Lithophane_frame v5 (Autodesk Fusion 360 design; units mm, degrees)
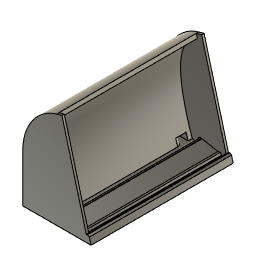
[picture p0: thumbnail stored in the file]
sketch "Sketch1" plane through (0, 0, 0) normal (0, 1, 0) x axis (1, 0, 0)
  line L1 (-20, -10) -> (0, -6)
  line L2 (-68.8984, 0) -> (-68.8984, -60)
  line L3 (16.1016, 0) -> (-68.8984, 0)
  line L4 (13.523, -9.6235) -> (16.1016, 0)
  line L5 (22.5, 0) -> (1.75, 0)
  line L6 (0, -22.5) -> (0, -1.75)
  line L7 (-20.1396, -121.7309) -> (-26.9011, -119.9192)
  line L8 (10.9187, -5.8198) -> (-20.1396, -121.7309)
  line L9 (4.1572, -4.0081) -> (10.9187, -5.8198)
  line L10 (-26.9011, -119.9192) -> (4.1572, -4.0081)
  line L11 (8.469, -1.439) -> (2.4963, -23.7296)
  line L12 (10.9187, -5.8198) -> (10.1422, -8.7176)
  line L13 (10.9187, -5.8198) -> (10.1422, -8.7176)
  line L14 (10.9187, -5.8198) -> (4.1572, -4.0081)
  line L15 (3.3807, -6.9059) -> (4.1572, -4.0081)
  line L16 (10.1422, -8.7176) -> (13.523, -9.6235)
  line L17 (0, -6) -> (3.3807, -6.9059)
  line L18 (-25.607, -115.0896) -> (-26.9011, -119.9192)
  line L19 (-25, -10) -> (-20, -10)
  line L20 (-25, -4) -> (-25, -10)
  line L21 (-32, -4) -> (-25, -4)
  curve K1 (-63.7939, -97.9077) -> (-25.607, -115.0896)
  curve K2 (-68.8984, -108.666) -> (-26.9011, -119.9192)
  line L22 (-45.6581, -60) -> (-68.8984, -60)
  point P3 (0, -6)
  point P14 (10.9187, -5.8198)
  point P15 (4.1572, -4.0081)
  point P2 (13.523, -9.6235)
  point P18 (10.1422, -8.7176)
  point P19 (3.3807, -6.9059)
  point P20 (-25.607, -115.0896)
  point P26 (-45.6581, -60)
  point P21 (-25, -10)
  point P22 (-25, -4)
  point P4 (-20, -10)
  point P12 (-26.9011, -119.9192)
  point P5 (-68.8984, -60)
  point P6 (-68.8984, 0)
  point P7 (16.1016, 0)
  point P23 (-32, -4)
  point P13 (-20.1396, -121.7309)
  perpendicular L2 L3
  perpendicular L4 L16
  collinear L3 L5
  coincident P3 L6
  perpendicular L7 L10
  perpendicular L7 L8
  perpendicular L8 L9
  parallel L4 L8
  parallel L4 L11
  symmetric P14 P15 L11
  symmetric P2 P3 L11
  coincident L8 P18
  coincident L10 P19
  coincident P19 L16
  collinear L16 L17
  coincident L10 P20
  perpendicular L7 L18
  horizontal L19
  perpendicular L19 L20
  perpendicular L20 L21
  coincident K1 P26
  perpendicular L2 L22
  dimension "d1" angle L3 L4 = 75
  dimension "d2" distance P2 P3 = 14
  dimension "d3" distance P3 L3 = 6
  dimension "d6" distance P14 P15 = 7
  dimension "d7" distance L9 L16 = 3
  dimension "d9" distance P21 P22 = 6
  dimension "d10" distance P4 P21 = 5
  dimension "d11" distance P12 P20 = 5
  dimension "d12" distance P5 P6 = 60
  dimension "d13" distance P5 P26 = 23.2403
  dimension "d14" distance P6 P7 = 85
  dimension "d15" distance L3 L21 = 4
  dimension "d16" distance P22 P23 = 7
  dimension "d17" distance P3 L20 = 25
  dimension "d20" distance P13 P14 = 120
extrude "Extrude1" new body sketch "Sketch1" profile of L17 L1 L2 L3 L4 L5 L13 L14 L15 L18 L19 L20 L21 K1 K2 distance 171
sketch "Sketch2" plane through (-68.8984, 0, 0) normal (-1, 0, 0) x axis (0, -1, 0)
  line L1 (-85.5, 60) -> (85.5, 60)
  line L2 (-85.5, 0) -> (-85.5, 60)
  line L3 (85.5, 0) -> (-85.5, 0)
  line L4 (85.5, 60) -> (85.5, 0)
  line L5 (-3.5, 56) -> (-80.5, 56)
  line L6 (-3.5, 4) -> (-3.5, 56)
  line L7 (-80.5, 4) -> (-3.5, 4)
  line L8 (-80.5, 56) -> (-80.5, 4)
  point P6 (-80.5, 56)
  point P7 (-3.5, 56)
  point P9 (-80.5, 4)
  horizontal L5
  vertical L6
  horizontal L7
  vertical L8
  dimension "d21" distance P6 P7 = 77
  dimension "d22" distance P6 P9 = 52
  dimension "d23" distance L2 L8 = 5
  dimension "d24" distance L3 L7 = 4
extrude "Extrude2" cut sketch "Sketch2" profile of L5 L6 L7 L8 against normal blind 22
sketch "Sketch3" plane through (-46.8984, 0, 0) normal (-1, 0, 0) x axis (0, -1, 0)
  line L1 (-3.5, 4) -> (-80.5, 4)
  line L2 (-3.5, 56) -> (-3.5, 4)
  line L3 (-80.5, 4) -> (-80.5, 56)
  line L4 (-72.5, 4) -> (-80.5, 4)
  line L5 (-72.5, 12) -> (-72.5, 4)
  line L6 (-80.5, 12) -> (-72.5, 12)
  line L7 (-80.5, 4) -> (-80.5, 12)
  line L8 (-80.5, 56) -> (-3.5, 56)
  point P2 (-80.5, 4)
  point P6 (-80.5, 4)
  point P8 (-72.5, 12)
  point P9 (-80.5, 12)
  point P7 (-72.5, 4)
  horizontal L4
  vertical L5
  horizontal L6
  vertical L7
  coincident P2 P6
  dimension "d27" distance P8 P9 = 8
  dimension "d28" distance P7 P8 = 8
extrude "Extrude3" cut sketch "Sketch3" profile of L1 L3 L4 L5 L6 L7 against normal blind 16
fillet "Fillet1" radius 3
chamfer "Chamfer1" distance 2
fillet "Fillet2" radius 5
sketch "Sketch4" plane through (0, 85.5, 0) normal (0, 1, 0) x axis (-1, 0, 0)
  line L1 (-14.0406, 7.6916) -> (-11.5911, 9.1058)
  line L2 (-16.1016, 0) -> (-14.0406, 7.6916)
  line L3 (68.8984, 0) -> (-16.1016, 0)
  line L4 (68.8984, 60) -> (68.8984, 0)
  curve K1 (26.9011, 119.9192) -> (68.8984, 60)
  line L5 (25.607, 115.0896) -> (26.9011, 119.9192)
  curve K2 (32, 4) -> (25.607, 115.0896)
  line L6 (28, 4) -> (32, 4)
  line L7 (20.2971, 10) -> (22, 10)
  line L8 (0, 6) -> (19.7087, 9.9417)
  line L9 (-3.3807, 6.9059) -> (0, 6)
  line L10 (-4.1572, 4.0081) -> (-3.3807, 6.9059)
  line L11 (-10.9187, 5.8198) -> (-4.1572, 4.0081)
  line L12 (-10.1422, 8.7176) -> (-10.9187, 5.8198)
  line L13 (-11.5911, 9.1058) -> (-10.1422, 8.7176)
  line L14 (20.1716, 121.8504) -> (-10.1422, 8.7176)
  line L15 (26.9011, 119.9192) -> (20.1716, 121.8504)
  arc A1 centre (28, 7) radius 3 clockwise from (28, 4) to (25, 7)
  arc A2 centre (22, 7) radius 3 clockwise from (22, 10) to (25, 7)
  arc A3 centre (20.2971, 7) radius 3 clockwise from (19.7087, 9.9417) to (20.2971, 10)
  point P22 (-10.1422, 8.7176)
  point P23 (-10.1422, 8.7176)
  point P7 (26.9011, 119.9192)
  point P25 (26.9011, 119.9192)
  coincident P22 P23
  perpendicular L13 L14
  coincident P7 P25
extrude "Extrude4" add sketch "Sketch4" along normal blind 3
mirror "Mirror1" mirrorStitchTolerance 0.1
